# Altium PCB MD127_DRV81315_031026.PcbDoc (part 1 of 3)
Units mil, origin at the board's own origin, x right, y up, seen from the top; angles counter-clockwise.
Board outline 4400.04 x 2800.87 mil, 2 copper layers (Top Layer, Bottom Layer), stack 64.712 mil thick; 156 components, 62 nets, 376 pads, 751 vias.
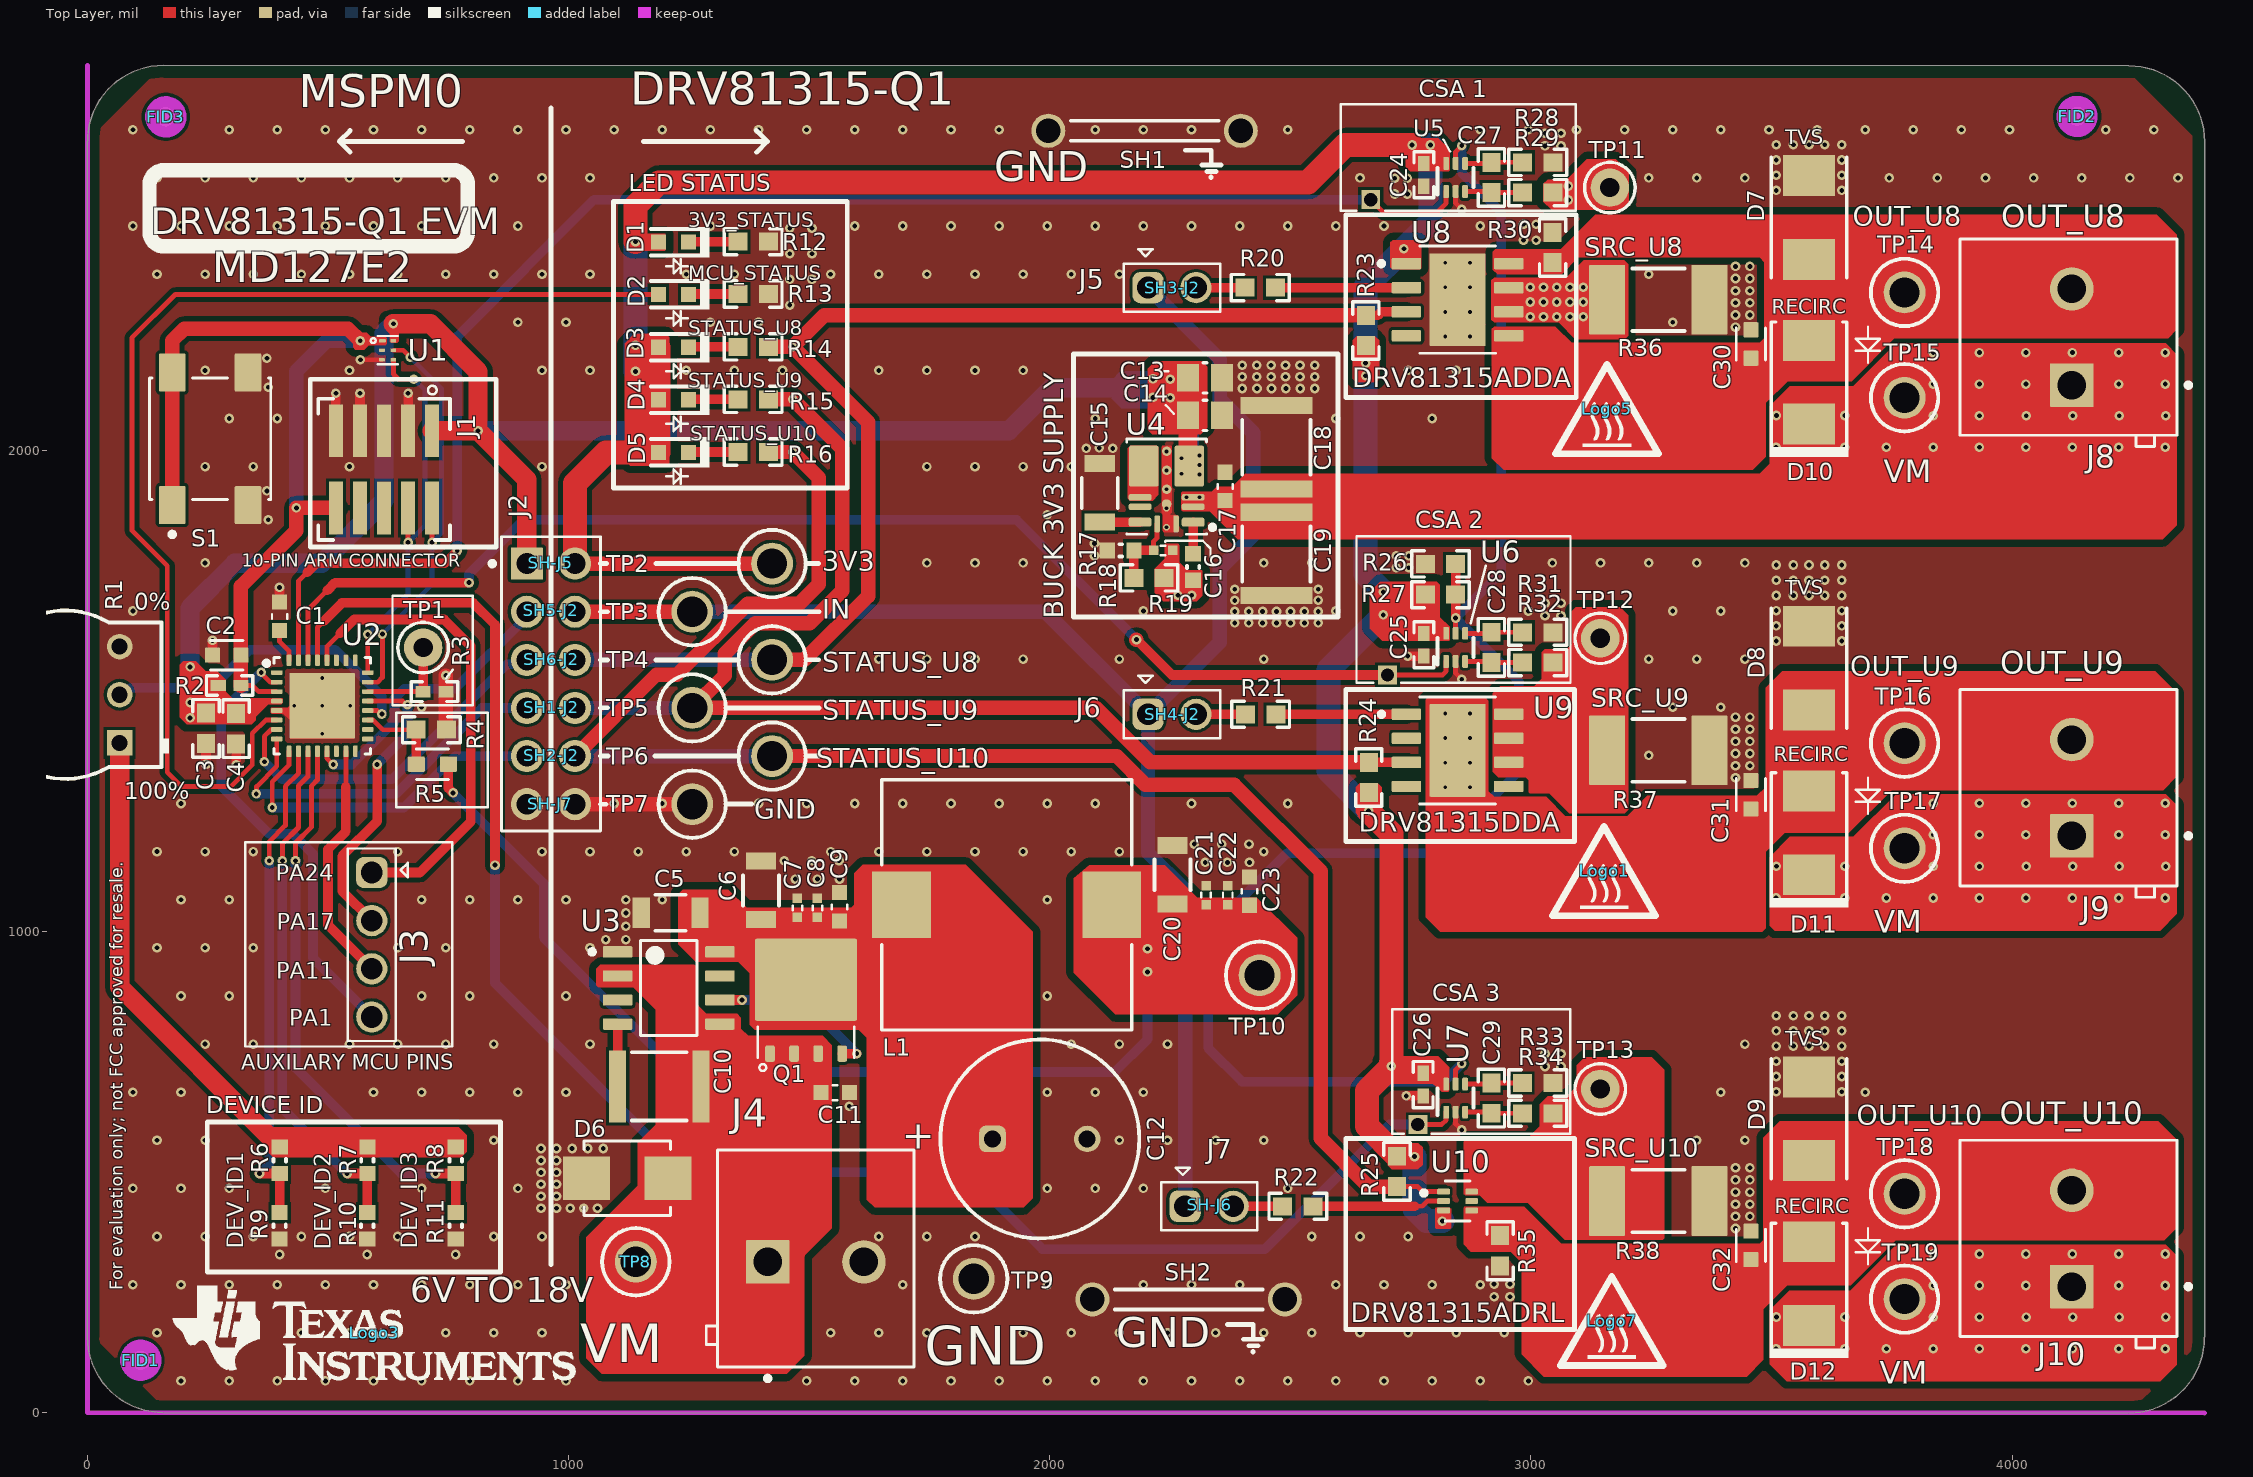
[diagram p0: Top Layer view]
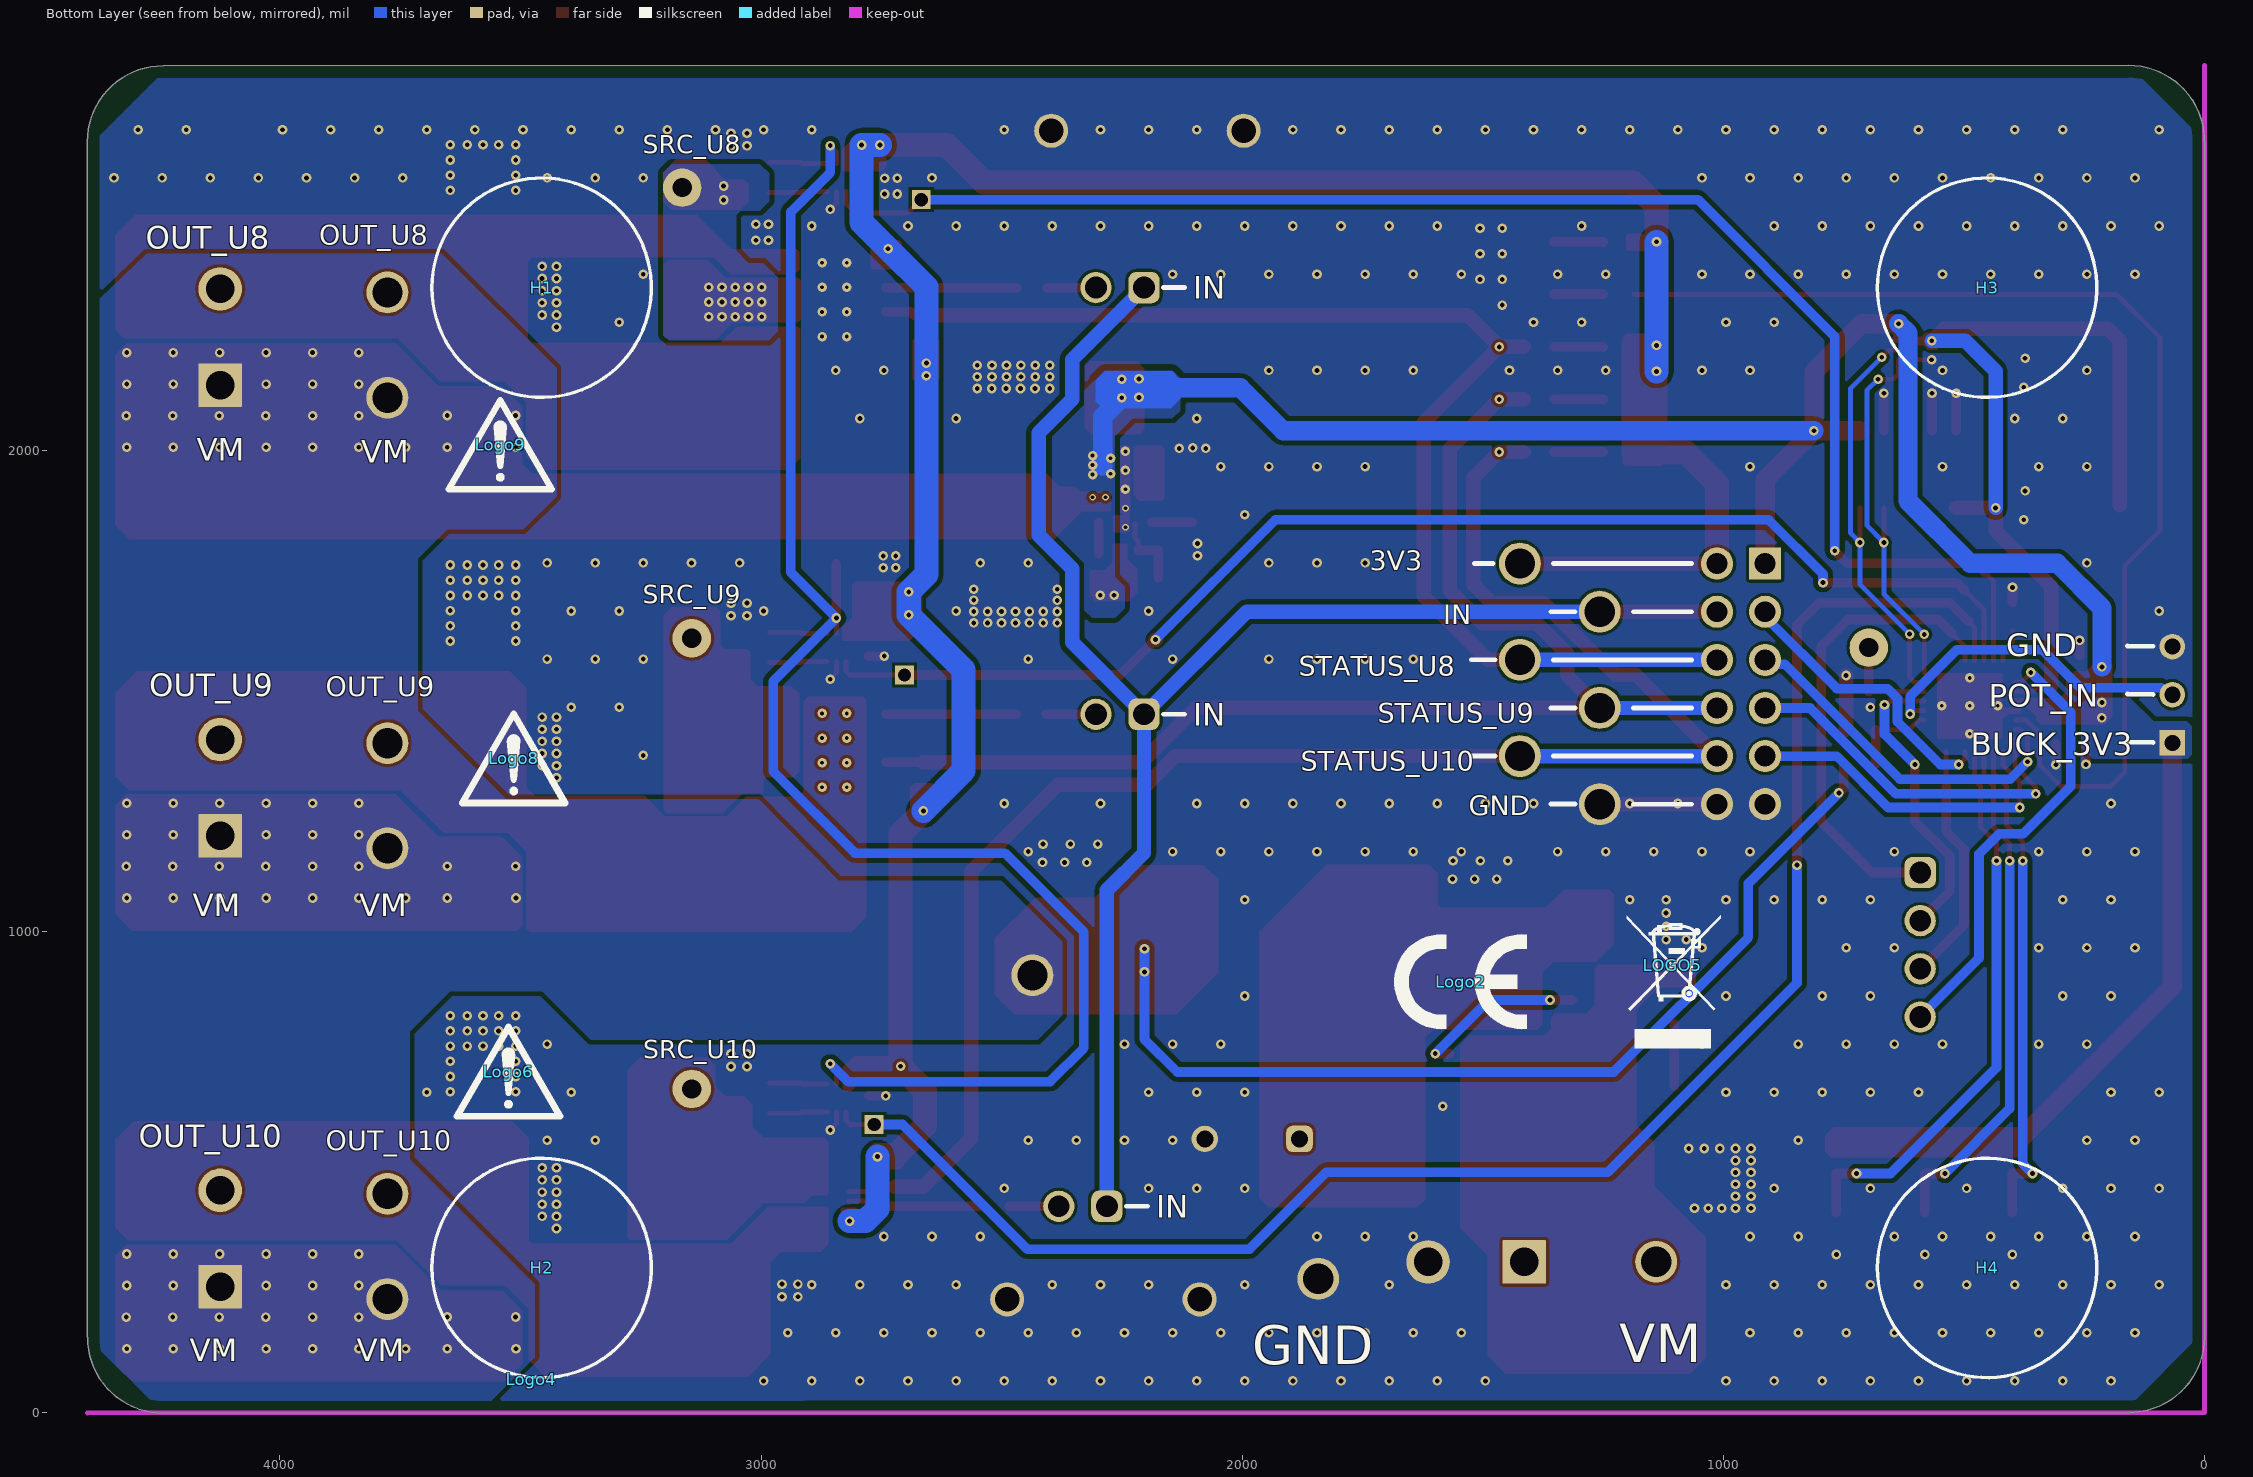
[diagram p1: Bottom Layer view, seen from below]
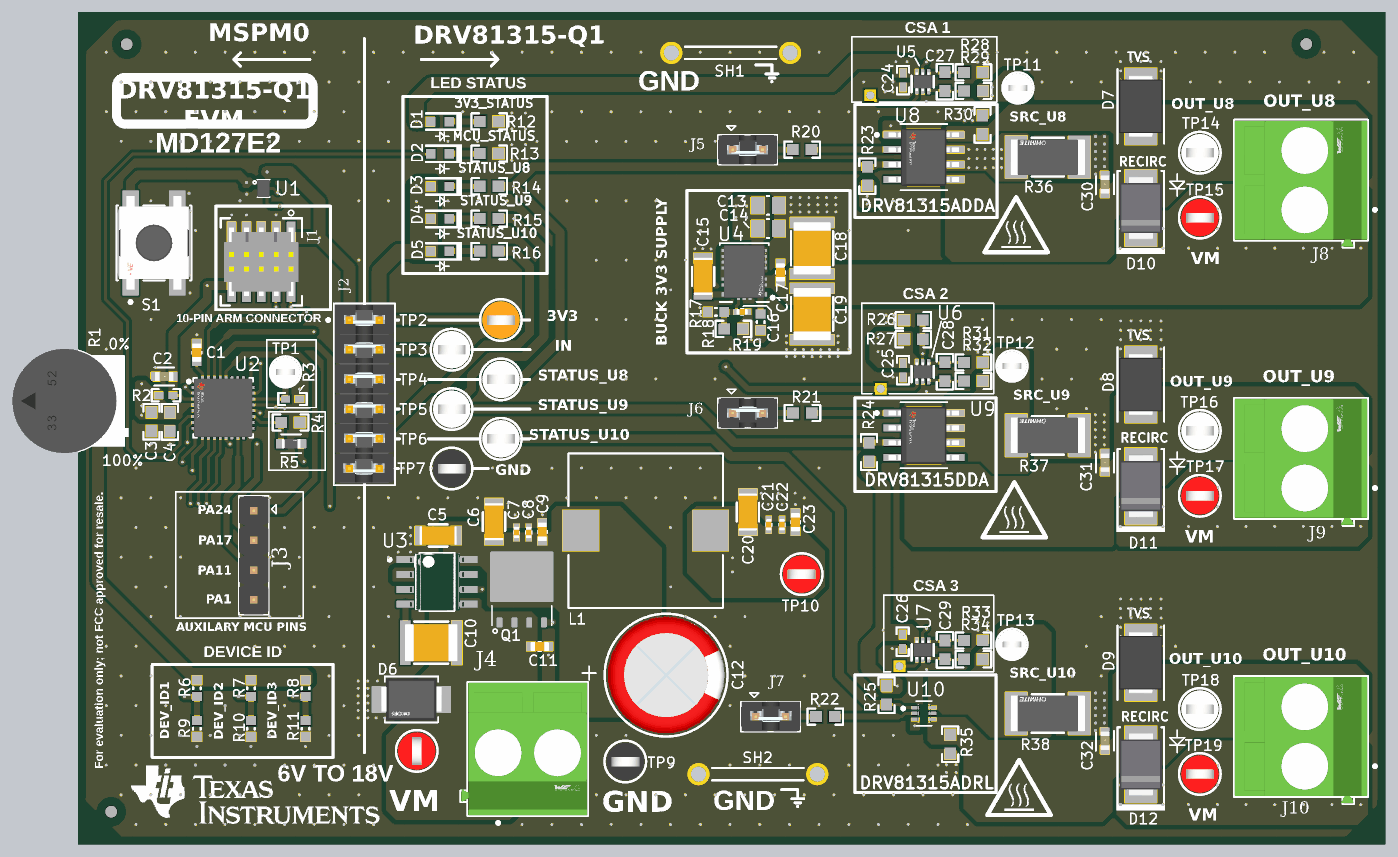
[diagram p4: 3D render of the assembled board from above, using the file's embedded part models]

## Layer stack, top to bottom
Top Solder: solder mask 0.4, Solder Resist, Dk 3.5
Top Layer: signal copper 2.756
Dielectric1: core 59.2, FR-4 High Tg, Dk 4.8
Bottom Layer: signal copper 2.756
Bottom Solder: solder mask 0.4, Solder Resist, Dk 3.5

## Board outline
157.47,0.36 cw(c157.47,157.84) -0.01,157.84 -0.04,157.84 0,2642.49 0.37,2642.49 cw(c157.85,2642.49) 157.85,2799.97 4242.57,2799.1 4242.52,2799.04 cw(c4242.52,2641.56) 4400,2641.56 4400,156.58 4399.59,156.58 cw(c4242.11,156.58) 4242.11,-0.9 4242.52,-0.9

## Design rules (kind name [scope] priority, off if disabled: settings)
AcuteAngle [All] p1: minimum=4.50000000000000E+0001 checktracksonly=FALSE
AssemblyTestPointUsage [All] p1: valid=2
BoardOutlineClearance BoardOutlineClearance_MountingHoles [OnCopper and InComponentClass('Mounting Holes')] p1: gap=15 ignorepadtopadclearanceinfootprint=FALSE
BoardOutlineClearance BoardOutlineClearance_Poly [OnCopper and IsPoly] p2: gap=25 ignorepadtopadclearanceinfootprint=FALSE
BoardOutlineClearance [OnCopper and Not InComponentClass('Logo') and not InComponentClass('FiducialMark') and not InRegion(1000,500,4000,800) and not InPoly] p3: gap=15 ignorepadtopadclearanceinfootprint=FALSE
Clearance [All] p1: gap=6 ignorepadtopadclearanceinfootprint=TRUE except(10: Track-Poly Poly-Poly; 15: Poly-Region)
Clearance Clearance_Keepouts [((IsTrack Or IsArc) And Not InPoly) And IsFree and IsKeepOut vs ((IsTrack Or IsArc) And Not InPoly) And IsFree and IsKeepOut] p2: gap=0 ignorepadtopadclearanceinfootprint=FALSE
Clearance Clearance_Poly [InPolygon] p3: gap=10 ignorepadtopadclearanceinfootprint=TRUE
Clearance Clearance_FiducialMark [IsKeepOut and InComponentClass('FiducialMark') vs IsPad and InComponentClass('FiducialMark')] p4: gap=0 ignorepadtopadclearanceinfootprint=TRUE
ComponentClearance ComponentClearance_Shunt [InComponentClass('Header') vs InComponentClass('Shunt')] p1: gap=0 collisioncheckmode=3 verticalgap=0 showdistances=FALSE
ComponentClearance ComponentClearance_PI_FILTER_R75 [InComponent('R75') vs InComponent('L1')] p2: gap=0 collisioncheckmode=3 verticalgap=0 showdistances=FALSE
ComponentClearance ComponentClearance_PI_FILTER_R66 [InComponent('R66') vs InComponent('L1')] p3: gap=0 collisioncheckmode=3 verticalgap=0 showdistances=FALSE
ComponentClearance ComponentClearance_CANL_Choke [InComponent('L2') vs InComponent('R71')] p4: gap=0 collisioncheckmode=3 verticalgap=0 showdistances=FALSE
ComponentClearance ComponentClearance_CANH_Choke [InComponent('L2') vs InComponent('R68')] p5: gap=0 collisioncheckmode=3 verticalgap=0 showdistances=FALSE
ComponentClearance ComponentClearance_MountingHoles_FiducialMarks [InComponentClass('Mounting Holes') vs InComponentClass('FiducialMark')] p6: gap=50 collisioncheckmode=3 verticalgap=10 showdistances=FALSE
ComponentClearance ComponentClearance_Logo [InComponentClass('Logo')] p7: gap=30 collisioncheckmode=3 verticalgap=10 showdistances=FALSE
ComponentClearance ComponentClearance_ScrewToNut [(HasFootprint('NY PMS 440 0025 PH')) vs (HasFootprint('Keystone_1902C'))] p8: gap=5 collisioncheckmode=3 verticalgap=10 showdistances=FALSE
ComponentClearance ComponentClearance_MountingHoles [InComponentClass('Mounting Holes')] p9: gap=100 collisioncheckmode=3 verticalgap=100000 showdistances=FALSE
ComponentClearance ComponentClearance_SmallPassives [HasFootprint('0201*') or HasFootprint('0402*') or HasFootprint('0508') or HasFootprint('0603*') or HasFootprint('0612') or HasFootprint('0805*') or HasFootprint('0815*') or HasFootprint('0830*') or HasFootprint('1206*') or HasFootprint('1210*') or HasFootprint('1808*') or HasFootprint('1812*') or HasFootprint('1825*') or HasFootprint('2010*') or HasFootprint('2220*') or HasFootprint('2225*') or HasFootprint('2512*') or HasFootprint('2728*') or HasFootprint('3518*') vs HasFootprint('0201*') or HasFootprint('0402*') or HasFootprint('0508') or HasFootprint('0603*') or HasFootprint('0612') or HasFootprint('0805*') or HasFootprint('0815*') or HasFootprint('0830*') or HasFootprint('1206*') or HasFootprint('1210*') or HasFootprint('1808*') or HasFootprint('1812*') or HasFootprint('1825*') or HasFootprint('2010*') or HasFootprint('2220*') or HasFootprint('2225*') or HasFootprint('2512*') or HasFootprint('2728*') or HasFootprint('3518*')] p10: gap=14.96 collisioncheckmode=3 verticalgap=10 showdistances=FALSE
ComponentClearance ComponentClearance_THtoSMT [IsThruComponent vs IsSMTComponent] p11: gap=30 collisioncheckmode=3 verticalgap=30 showdistances=FALSE
ComponentClearance ComponentClearance_THtoTH [IsThruComponent vs IsThruComponent] p12: gap=20 collisioncheckmode=3 verticalgap=30 showdistances=FALSE
ComponentClearance [All] p13: gap=20 collisioncheckmode=3 verticalgap=10 showdistances=FALSE
DiffPairsRouting [All] p1: maxlimit=100 minlimit=10 mostfreqgap=10 toplayer_minwidth=6 toplayer_maxwidth=15 toplayer_prefwidth=10 bottomlayer_minwidth=6 bottomlayer_maxwidth=15 bottomlayer_prefwidth=10 maxuncoupledlength=1000
FabricationTestPointUsage TestPointUsage [All] p1: valid=2 allowmultiple=FALSE
FabricationTestpoint Testpoint [All] p1: side=3 testpointundercomponent=TRUE minsize=40 maxsize=100 preferedsize=60 minholesize=0 maxholesize=40 preferedholesize=32 testpointgrid=1 allowsidetop=TRUE allowsidebottom=TRUE usegrid=TRUE gridtolerance=0.01
FanoutControl Fanout_LCC [IsLCC] p1: bgadir=Out bgaviamode=Centered fanoutstyle=Auto fanoutdirection=Alternating viagrid=1 // Fanout_LCC (Default Rule)
FanoutControl Fanout_BGA [IsBGA] p2: bgadir=Out bgaviamode=Centered fanoutstyle=Auto fanoutdirection=Alternating viagrid=1 // Fanout_BGA (Default Rule)
FanoutControl Fanout_Default [All] p4: bgadir=Out bgaviamode=Centered fanoutstyle=Auto fanoutdirection=Alternating viagrid=1 // Fanout_Default (Default Rule)
FanoutControl Fanout_Small [(CompPinCount < 5)] p5: bgadir=Out bgaviamode=Centered fanoutstyle=Auto fanoutdirection=OutThenIn viagrid=1 // Fanout_Small (Default Rule)
HoleSize [All] p1: absolutevalues=TRUE maxlimit=251 minlimit=7.87 maxpercent=80.000 minpercent=20.000
MinimumAnnularRing MinimumAnnularRing_ThermalPadVias [IsVia and InAnyComponent] p1: minimumring=5.91
MinimumAnnularRing [All] p2: minimumring=5.91
MinimumSolderMaskSliver MinimumSolderMaskSliver_Logo [InComponentClass('Logo') vs InComponentClass('Logo')] p1: minsoldermaskwidth=0.7
MinimumSolderMaskSliver [All] p2: minsoldermaskwidth=3.94
PlaneClearance [All] p1: clearance=10
PlaneConnect [All] p1: planeconnectstyle=Direct reliefexpansion=10 reliefentries=4 reliefconductorwidth=10 reliefairgap=10
PolygonConnect [All] p1: connectstyle=Direct reliefconductorwidth=10 reliefentries=4 polygonreliefangle="90 Angle" airgapwidth=10
RoutingVias ThermalPadVias [IsVia and InAnyComponent] p1: holewidth=7.87 width=19.68 viastyle="Through Hole" minholewidth=7.87 minwidth=19.68 maxholewidth=12.99 maxwidth=23.62
RoutingVias [All] p2: holewidth=16 width=34 viastyle="Through Hole" minholewidth=7.87 minwidth=19.68 maxholewidth=236.22 maxwidth=236.22
SilkToBoardRegionClearance [Not ((IsComment or IsDesignator) And (Hide <> 'False')) and not InRegion(1000,500,4000,800)] p1:
SilkToSilkClearance SilkToSilkClearance_Pb-FreeLogo [(HasFootprint('Pb-Free_Overlay_Medium') OR HasFootprint('Pb-Free_Overlay_Small')) vs (HasFootprint('Pb-Free_Overlay_Medium') OR HasFootprint('Pb-Free_Overlay_Small'))] p1: silktosilkclearance=0
SilkToSilkClearance [All] p2: silktosilkclearance=3.94
SilkToSolderMaskClearance SilkToComponentPadClearance [(IsPad or IsFill or IsRegion) and InAnycomponent] p1: minsilkscreentomaskgap=5 clearancetoexposedcopper=TRUE
SilkToSolderMaskClearance "Silk to Solder Mask Opening" [All] p2: minsilkscreentomaskgap=3.94 clearancetoexposedcopper=FALSE
SolderMaskExpansion [All] p1: expansion=1.97 istentingtop=FALSE
UnRoutedNet [All] p1: checkbadconnections=TRUE
Width [All] p1: maxlimit=100 minlimit=6 preferedwidth=10 checkconnectedcopper=TRUE
13 further rules are at their usual default settings.

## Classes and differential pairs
component class DRV81315-Q1_HW: !PCB1 FID1 FID2 FID3 H1 H2 H3 H4 Logo1 Logo2 Logo3 Logo4 LOGO5 Logo6 ZZ1 ZZ2 ZZ3 ZZ4
component class DRV81315AQ1_ICs: 15 C24 C25 C26 C27 C28 C29 C30 C31 C32 D7 D8 D9 D10 D11 D12 J5 J6 J7 J8 J9 J10 L? R20 R21 R22 R23 R24 R25 R26 R27 R28 R29 R30 R31 R32 R33 R34 R35 R36 R37 R38 SH1 SH2 SH-J5 SH-J6 SH-J7 TP11 TP12 TP13 TP14 TP15 TP16 TP17 TP18 TP19 U5 U6 U7 U8 U9 U10
component class DRV81315-Q1_MCU_Supply: C1 C2 C3 C4 C5 C6 C7 C8 C9 C10 C11 C12 C13 C14 C15 C16 C17 C18 C19 C20 C21 C22 C23 D1 D2 D3 D4 D5 D6 J1 J2 J3 J4 l1 Q1 R1 R2 R3 R4 R5 R6 R7 R8 R9 R10 R11 R12 R13 R14 R15 R16 R17 R18 R19 S1 SH1-J2 SH2-J2 SH3-J2 SH4-J2 SH5-J2 SH6-J2 TP1 TP2 TP3 TP4 TP5 TP6 TP7 TP8 TP9 TP10 U1 U2 U3 U4

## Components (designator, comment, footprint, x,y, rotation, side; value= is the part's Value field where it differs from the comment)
C1 "885012206075R" WCAP-CSGP_0603_L1.6W0.8H0.8_REFLOW 399.1,1654.99 r270 top value=470nF
C2 "885012206065" FP-885012206065_0603-MFG 289.54,1574.33 r180 top value=10nF
C3 "GRM188R61E106KA73D" 0603 246.51,1422.21 r270 top value=10uF
C4 "885012206095" 0603 309,1421.5 r270 top value=0.1uF
C5 "885012208093" WCAP-CSGP_1206_L3.2W1.6H1.6 1212,1039 r0 top
C6 "885012208093" WCAP-CSGP_1206_L3.2W1.6H1.6 1399.91,1085.54 r270 top
C7 "885012205067" WCAP-CSGP_0402_L1W0.5H0.5 1475.5,1049.2 r270 top
C8 "885012205061" WCAP-CSGP_0402_L1W0.5H0.5 1516.92,1049.2 r270 top
C9 "885012206095" WCAP-CSGP_0603_L1.6W0.8H0.8_REFLOW 1562.71,1051.38 r270 top
C10 "885012210032" WCAP-CSGP_1812_L4.5W3.2H2.5 1188.46,678.32 r0 top
C11 "885012206091" WCAP-CSGP_0603_L1.6W0.8H0.8_REFLOW 1554,665.09 r180 top
C12 "860040875004" WCAP-ATUL_D10H20 1979.38,568.96 r180 top
C13 "885012107014" 0805_150 2322.72,2150.59 r0 top value=10uF
C14 "885012107014" 0805_150 2322.72,2072.53 r0 top value=10uF
C15 "885012208093" WCAP-CSGP_1206_L3.2W1.6H1.6 2103.93,1911.73 r270 top
C16 "885012005029" WCAP-CSGP_0402_L1W0.5H0.5 2235.56,1792.13 r0 top
C17 "885012206095" WCAP-CSGP_0603_L1.6W0.8H0.8_REFLOW 2364.37,1924.96 r270 top
C18 "885012210032" WCAP-CSGP_1812_L4.5W3.2H2.5 2471.06,2006.19 r270 top
C19 "885012210032" WCAP-CSGP_1812_L4.5W3.2H2.5 2471.06,1784.67 r90 top
C20 "885012208093" WCAP-CSGP_1206_L3.2W1.6H1.6 2255,1118 r270 top
C21 "885012205067" WCAP-CSGP_0402_L1W0.5H0.5 2324.7,1075.68 r270 top
C22 "885012205061" WCAP-CSGP_0402_L1W0.5H0.5 2369.89,1075.68 r270 top
C23 "885012206095" WCAP-CSGP_0603_L1.6W0.8H0.8_REFLOW 2414.78,1084.07 r270 top
C24 "885012105001" 0402 2777.36,2572.55 r90 top value=0.1uF
C25 "885012105001" 0402 2777.36,1595.92 r90 top value=0.1uF
C26 "885012105001" 0402 2775.95,681.93 r90 top value=0.1uF
C27 "885012206046" 0603 2917.89,2567.04 r90 top value=0.1uF
C28 "885012206046" 0603 2917.89,1590.41 r90 top value=0.1uF
C29 "885012206046" 0603 2917.89,653.78 r90 top value=0.1uF
C30 "885012206091" FP-885012206091_0603-MFG 3457,2221 r270 top value=22nF
C31 "885012206091" FP-885012206091_0603-MFG 3457,1284.37 r270 top value=22nF
C32 "885012206091" FP-885012206091_0603-MFG 3457,347.74 r270 top value=22nF
D1 "150060VS75000" WL-SMCW_GREEN 1218.01,2432.69 r180 top value=Green
D2 "150060VS75000" WL-SMCW_GREEN 1218.01,2324.12 r180 top value=Green
D3 "150060RS75000" WL-SMCW_RED 1218.01,2214.23 r180 top value=Red
D4 "150060RS75000" WL-SMCW_RED 1218.01,2105 r180 top value=Red
D5 "150060RS75000" WL-SMCW_RED 1218.01,1995.77 r180 top
D6 "SMBJ36CA-13-F" FP-SMBJ36CA-13-F_SMB-MFG 1122,487.09 r180 top
D7 "SMBJ33CA-13-F" SMB-Bi 3577.88,2484.01 r270 top value=33V
D8 "SMBJ33CA-13-F" SMB-Bi 3577.88,1547.38 r270 top value=33V
D9 "SMBJ33CA-13-F" SMB-Bi 3577.88,610.74 r270 top value=33V
D10 "SS24T3G" SMB 3577.88,2141.62 r90 top value=40V
D11 "SS24T3G" SMB 3577.88,1204.99 r90 top value=40V
D12 "SS24T3G" SMB 3577.88,268.36 r90 top value=40V
FID1 "Fiducial" Fiducial10-20 111,109 r0 top
FID2 "Fiducial" Fiducial10-20 4135,2693.92 r0 top
FID3 "Fiducial" Fiducial10-20 163,2693 r0 top
H1 "SJ-5303 (CLEAR)" Bumpon_SJ5003Transparent 3456,2338 r180 bottom
H2 "SJ-5303 (CLEAR)" Bumpon_SJ5003Transparent 3456,301 r180 bottom
H3 "SJ-5303 (CLEAR)" Bumpon_SJ5003Transparent 452,2338 r180 bottom
H4 "SJ-5303 (CLEAR)" Bumpon_SJ5003Transparent 452,301 r180 bottom
J1 "FTSH-105-01-L-DV-K" SAMTEC_FTSH-105-01-X-DV-K 616.46,1960.48 r270 top
J2 "61301221121" FP-61301221121_HDR12-MFG 963.3,1514.56 r270 top
J3 "61300411121" WURTH_61300411121 591,972.52 r270 top
J4 "691236510002" FP-691236510002_HHR2-MFG#1 1501.92,320.2 r0 top
J5 "61300211121" WURTH_61300211121 2254.12,2338.11 r0 top
J6 "61300211121" WURTH_61300211121 2254.12,1451.48 r0 top
J7 "61300211121" WURTH_61300211121 2331.28,429 r0 top
J8 "691236510002" FP-691236510002_HHR2-MFG#2 4117.18,2223.6 r90 top
J9 "691236510002" FP-691236510002_HHR2-MFG#2 4117.18,1286.97 r90 top
J10 "691236510002" FP-691236510002_HHR2-MFG#2 4117.18,350.33 r90 top
L1 "74437377010" WE-LHMI_1335 1910.49,1055.44 r0 top value=1uH
Logo1 "CAUTION HOT SURFACE" IEC_HotSurface_Small 3152,1126 r0 top (schematic designator LOGO1)
Logo2 "CE Mark" CE_Mark_5mm 1546.13,895.63 r180 bottom
Logo3 "Texas Instruments" TI_Stacked_Overlay_Small 596,166 r0 top
Logo4 "FCC disclaimer" FCC_disclaimer 3478,69.09 r180 bottom
Logo5 "CAUTION HOT SURFACE" IEC_HotSurface_Small 3158,2086 r0 top (schematic designator LOGO1)
LOGO5 "WEEE logo" WEEE_Minimum 1105.27,929.45 r180 bottom (schematic designator Logo5)
Logo6 "CAUTION.  READ USER GUIDE BEFORE USE" IEC_Caution_Small 3525,709 r180 bottom
Logo7 "CAUTION HOT SURFACE" IEC_HotSurface_Small 3168,191 r0 top (schematic designator LOGO1)
Logo8 "CAUTION.  READ USER GUIDE BEFORE USE" IEC_Caution_Small 3514,1360 r180 bottom (schematic designator Logo6)
Logo9 "CAUTION.  READ USER GUIDE BEFORE USE" IEC_Caution_Small 3542,2012 r180 bottom (schematic designator Logo6)
Q1 "CSD19502Q5B" DNK0008A 1493.58,857.23 r90 top value=80V
R1 "3352T-1-503LF" Bourns_3352T 67,1492.09 r90 top value=50k
R2 "CRCW040247K0JNED" 0402 295.45,1511.18 r180 top value=47k
R3 "CRCW040247K0JNED" 0402 721.37,1498.53 r180 top value=47k
R4 "RC0603JR-071KL" 0603 714.83,1419.47 r180 top value=1.0k
R5 "RT0603BRE078KL" FP-RT0603BRE078KL_0603-MFG 716.83,1347.75 r0 top value=8k
R6 "RC0603JR-0710KL" 0603L 399.78,524.72 r270 top value=10k
R7 "RC0603JR-0710KL" 0603L 581.76,524.72 r270 top value=10k
R8 "RC0603JR-0710KL" 0603L 765.55,524.72 r270 top value=10k
R9 "RC0603JR-0710KL" 0603L 399.48,388.42 r270 top value=10k
R10 "RC0603JR-0710KL" 0603L 581.6,388.42 r270 top value=10k
R11 "RC0603JR-0710KL" 0603L 765.55,388.42 r270 top value=10k
R12 "RC0603FR-071KL" 0603 1383.61,2433.49 r180 top value=1.00k
R13 "RC0603JR-07330RL" 0603 1383.62,2324.91 r180 top value=330
R14 "RC0603JR-07330RL" 0603 1383.61,2215.03 r180 top value=330
R15 "RC0603JR-07330RL" 0603 1383.61,2105.8 r180 top value=330
R16 "RC0603JR-07330RL" 0603 1383.61,1996.56 r180 top value=330
R17 "RC0603JR-0710KL" 0603L 2147.14,1792.13 r0 top value=10k
R18 "RC0603FR-0723K2L" 0603 2206.2,1734.88 r0 top value=23.2k
R19 "RC0603JR-0710KL" 0603L 2297.87,1757.52 r270 top value=10k
R20 "RC0603FR-071KL" 0603 2437.45,2338.11 r0 top value=1.00k
R21 "RC0603FR-071KL" 0603 2438.34,1451.48 r0 top value=1.00k
R22 "RC0603FR-071KL" 0603 2515.5,429 r0 top value=1.00k
R23 "RC0603FR-074K99L" 0603 2657,2249 r90 top value=4.99k
R24 "RC0603FR-074K99L" 0603 2663,1319.98 r90 top value=4.99k
R25 "RC0603FR-074K99L" 0603 2721.62,501.41 r270 top value=4.99k
R26 "RC0603FR-07200RL" 0603 2811.87,1764 r0 top value=200
R27 "RC0603FR-07200RL" 0603 2811.87,1700 r180 top value=200
R28 "ERJ-3GEY0R00V" 0603 3014.16,2598.54 r180 top value=0
R29 "ERJ-3GEY0R00V" 0603 3014.16,2535.54 r180 top value=0
R30 "RC0603FR-07100KL" 0603 3045,2421.5 r270 top value=100k
R31 "ERJ-3GEY0R00V" 0603 3014.16,1621.9 r180 top value=0
R32 "ERJ-3GEY0R00V" 0603 3014.16,1558.91 r180 top value=0
R33 "ERJ-3GEY0R00V" 0603 3014.16,685.27 r180 top value=0
R34 "ERJ-3GEY0R00V" 0603 3014.16,622.28 r180 top value=0
R35 "RC0603FR-07100KL" 0603 2936,336.5 r90 top value=100k
R36 "PCS2512DR0100ET" FP-PCS2512DR0100ET_2512-MFG 3264.7,2313.11 r180 top
R37 "PCS2512DR0100ET" FP-PCS2512DR0100ET_2512-MFG 3264.7,1376.48 r180 top
R38 "PCS2512DR0100ET" FP-PCS2512DR0100ET_2512-MFG 3264.7,439.84 r180 top
S1 "430481025816" FP-430481025816_SMT_SW_6MM2_6MM2-MFG 255,2024 r90 top
SH1 "Jumper_2p" Harwin_D3082-05 2197,2664.09 r180 top
SH1-J2 "60900213421" Wurth_60900213421 963.77,1466.24 r0 top
SH2 "Jumper_2p" Harwin_D3082-05 2288.48,235.42 r180 top
SH2-J2 "60900213421" Wurth_60900213421 963.77,1366.24 r0 top
SH3-J2 "60900213421" Wurth_60900213421 2254.12,2338.11 r180 top
SH4-J2 "60900213421" Wurth_60900213421 2254.12,1451.48 r0 top
SH5-J2 "60900213421" Wurth_60900213421 963.3,1667.74 r0 top
SH6-J2 "60900213421" Wurth_60900213421 963.77,1566.24 r0 top
SH-J5 "60900213421" Wurth_60900213421 963.3,1766.34 r180 top
SH-J6 "60900213421" Wurth_60900213421 2332.29,432.05 r180 top
SH-J7 "60900213421" Wurth_60900213421 962.02,1265.79 r180 top
TP1 "5002" Keystone5002 697.75,1590 r90 top
TP2 "5013" Keystone5013 1422.91,1764.69 r90 top
TP3 "5012" Keystone5012 1257.04,1664.69 r90 top
TP4 "5012" Keystone5012 1422.91,1564.69 r90 top
TP5 "5012" Keystone5012 1257.04,1464.69 r90 top
TP6 "5012" Keystone5012 1422.91,1364.69 r90 top
TP7 "5011" Keystone5011 1257.04,1264.69 r90 top
TP8 "5010" Keystone5010 1139.79,313.78 r0 top
TP9 "5011" Keystone5011 1842,278.09 r90 top
TP10 "5010" Keystone5010 2436,909 r270 top
TP11 "5002" Keystone5002 3164,2546 r90 top
TP12 "5002" Keystone5002 3144,1609.37 r90 top
TP13 "5002" Keystone5002 3144,672.74 r90 top
TP14 "5012" Keystone5012 3776.4,2328.08 r90 top
TP15 "5010" Keystone5010 3776.4,2109.4 r90 top
TP16 "5012" Keystone5012 3776.4,1391.45 r90 top
TP17 "5010" Keystone5010 3776.4,1172.77 r90 top
TP18 "5012" Keystone5012 3776.4,454.82 r90 top
TP19 "5010" Keystone5010 3776.4,236.14 r90 top
U1 "TPD4E004DRYR" DRY0006A 624,2208 r0 top
U2 "MSPM0G3507SRHB" RHB0032E-MFG 488,1469 r0 top
U3 "LM74700QDRQ1" D0008A-MFG 1208.15,882.65 r0 top
U4 "TPSM365R3FRDNR" RDN0011A-MFG 2242.76,1927.95 r180 top
U5 "INA185A2IDRLR" DRL0006A 2843.37,2567.04 r90 top
U6 "INA185A2IDRLR" DRL0006A 2843.37,1590.41 r90 top
U7 "INA185A2IDRLR" DRL0006A 2843.37,653.78 r90 top
U8 "DRV81315ADDA" DDA0008B-MFG 2847.5,2313.11 r0 top
U9 "DRV81315DDA" DDA0008B-MFG 2847.5,1376.48 r0 top
U10 "DRV81315ADRL" DRL0006A-MFG 2847.5,439.84 r0 top
ZZ1 "This Assembly Note is for PCB labels only" AssemblyNoteLabel -521.96,6760.09 r0 top
ZZ2 "These assemblies are ESD sensitive, ESD precautions shall be observed." AssemblyNote -517,6642.09 r0 top
ZZ3 "These assemblies must be clean and free from flux and all contaminants. Use of no clean flux is not acceptable." AssemblyNote -518,6517.09 r0 top
ZZ4 "These assemblies must comply with workmanship standards IPC-A-610 Class 2, unless otherwise specified." AssemblyNote -518,6372.09 r0 top

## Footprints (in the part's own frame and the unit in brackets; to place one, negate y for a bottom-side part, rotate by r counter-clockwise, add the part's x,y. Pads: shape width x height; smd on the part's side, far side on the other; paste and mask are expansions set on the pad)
0402 [mm] "0402 from SM-752 data"
  rect 0.8x0.6 smd: 1(-0.6,0) 2(0.6,0)
  silkscreen extent -1.22,-0.52 1.22,0.52, body extent -0.55,-0.3 0.55,0.3, height 0.6
0603 [mm] "0603 from SM-752 data"
  rect 1x0.95 smd: 1(-0.8,0) 2(0.8,0)
  silkscreen extent -1.52,-0.69 1.52,0.69, body extent -0.87,-0.47 0.87,0.47, height 1
0603L [mm] "0603 from SM-752 data"
  rect 0.8x0.85 smd: 1(-0.7,0) 2(0.7,0)
  silkscreen extent -0.07,-0.33 0.07,0.33, body extent -0.87,-0.47 0.87,0.47, height 1
0805_150 [mm] "0805 / 1.5 mm height"
  rect 1.15x1.45 smd: 1(-0.9,0) 2(0.9,0)
  silkscreen extent -0.1,-0.8 0.1,0.8, body extent -1.1,-0.72 1.1,0.72, height 1.5
AssemblyNote [mil] "Assembly Note"
AssemblyNoteLabel [mil] "Assembly Note for PCB Labels"
Bourns_3352T [mm] "TH, 3-Leads, Body 9.53x8.89mm, Pitch 2.54mm"
  rect 1.35x1.35 hole 0.85: 1(-2.54,0)
  round 1.35 hole 0.85: 2(0,0) 3(2.54,0)
  silkscreen extent -4.44,-2.6 4.44,7.31, body extent -4.44,-2.21 4.45,7.32, height 3.81
Bumpon_SJ5003Transparent [mil] "3M Hemispherical Bumpon transparent"
  round 1 on Mech4: 0(0,0)
  silkscreen extent -228,-228 228,228, body extent -219,-219 219,219, height 197
CE_Mark_5mm [mil] "Minimum text height for CE Mark"
  silkscreen extent -138,-98 138,98
D0008A-MFG [mm] "Recommended Land Pattern"
  rrect17% 1.55x0.6 smd paste+0 mask+0: 1(-2.7,1.905) 2(-2.7,0.635) 3(-2.7,-0.635) 4(-2.7,-1.905) 5(2.7,-1.905) 6(2.7,-0.635) 7(2.7,0.635) 8(2.7,1.905)
  silkscreen extent -4.17,-2.5 1.5,2.5, body extent -3,-2.45 3,2.45, height 1.75
DDA0008B-MFG [mm] "Recommended Land Pattern"
  rrect17% 1.55x0.6 smd: 1(-2.7,1.905) 2(-2.7,0.635) 3(-2.7,-0.635) 4(-2.7,-1.905) 5(2.7,-1.905) 6(2.7,-0.635) 7(2.7,0.635) 8(2.7,1.905)
  rrect3% 2.95x4.9 smd: 9(0,0)
  silkscreen extent -4.15,-2.83 2,2.83, body extent -3.01,-2.45 3.01,2.45, height 1.7
DNK0008A [mm] "SON, 8-Leads, Body 5x6mm"
  rrect39% 0.86x0.51 smd paste+0 mask+0: 1(-2.82,1.905) 2(-2.82,0.635) 3(-2.82,-0.635) 4(-2.82,-1.905)
  rrect39% 0.86x0.51 smd paste-0.05 mask-0.05: 5(2.82,-1.905) 6(2.82,-0.635) 7(2.82,0.635) 8(2.82,1.905)
  rrect50% 0.25x0.555 on Top Paste: 9(-0.83,2.372) 9(-0.83,-2.372)
  rrect50% 0.25x0.555 on Top Solder: 9(-0.83,2.372) 9(-0.83,-2.372)
  rrect50% 0.95x1.13 on Top Paste: 9(-0.535,0) 9(-0.535,1.33) 9(-0.535,-1.33) 9(0.615,0) 9(0.615,-1.33) 9(0.615,1.33) 9(1.765,-1.33) 9(1.765,1.33) 9(1.765,0)
  rrect50% 3.58x4 on Top Solder: 9(0.75,0)
  rrect5% 4.34x5.4 smd paste+0 mask+0: 9(1.08,0)
  silkscreen extent -3.74,-2.55 -1.41,2.55, body extent -3.05,-2.55 3.05,2.55, height 1.06
DRL0006A [mm] "SOTFL, 6-Flat Leads, Body 1.2x1.6x0.6mm, Pitch 0.5mm, TI recommended"
  rrect33% 0.67x0.3 smd: 1(-0.74,0.5) 2(-0.74,0) 3(-0.74,-0.5) 4(0.74,-0.5) 5(0.74,0) 6(0.74,0.5)
  silkscreen extent -0.9,-0.95 0.5,0.95, body extent -0.8,-0.8 0.8,0.8, height 0.61
DRL0006A-MFG [mm] "Recommended Land Pattern"
  rrect33% 0.67x0.3 smd: 1(-0.74,0.5) 2(-0.74,0) 3(-0.74,-0.5) 4(0.74,-0.5) 5(0.74,0) 6(0.74,0.5)
  silkscreen extent -1.9,-1.05 0.65,1.05, body extent -0.8,-0.8 0.8,0.8, height 0.6
DRY0006A [mm] "PSON, 6-Leads, Body 1x1.45mm, Pitch 0.5mm, TI Recommended"
  rrect50% 0.35x0.2 smd mask+0.038: 1(-0.275,0.5)
  rrect50% 0.3x0.2 smd mask+0.038: 2(-0.3,0) 3(-0.3,-0.5) 4(0.3,-0.5) 5(0.3,0) 6(0.3,0.5)
  silkscreen extent -0.89,-0.75 0.53,0.75, body extent -0.5,-0.72 0.5,0.73, height 0.58
FCC_disclaimer [mil]
Fiducial10-20 [mm]
  round 1 smd: 1(0,0)
  Top Layer keep-out circle w1.178: c0,0 r0.5
FP-61301221121_HDR12-MFG [mm]
  rrect6% 1.7x1.7 hole 1.1 paste-2539.97 mask+0: 1(-6.35,-1.27)
  round 1.7 hole 1.1 paste-2539.97 mask+0: 2(-6.35,1.27) 3(-3.81,-1.27) 4(-3.81,1.27) 5(-1.27,-1.27) 6(-1.27,1.27) 7(1.27,-1.27) 8(1.27,1.27) 9(3.81,-1.27) 10(3.81,1.27) 11(6.35,-1.27) 12(6.35,1.27)
  silkscreen extent -7.77,-3.22 7.77,2.62, body extent -7.87,-2.72 7.87,2.72, height 0.25
FP-430481025816_SMT_SW_6MM2_6MM2-MFG [mm]
  rrect7% 2x1.4 smd paste+0 mask+0: 1(-3.5,2) 2(3.5,2) 3(-3.5,-2) 4(3.5,-2)
  silkscreen extent -5.17,-3.2 3.2,3.2, body extent -4.6,-3.3 4.6,3.3, height 0.25
FP-691236510002_HHR2-MFG#1 [mm]
  rrect4% 2.3x2.3 hole 1.5 paste-2539.97 mask+0: 1(-2.24,-0.175)
  round 2.3 hole 1.5 paste-2539.97 mask+0: 2(2.84,-0.175)
  silkscreen extent -5.48,-6.45 5.48,5.72, body extent -5.58,-5.82 5.58,5.82, height 0.25
FP-691236510002_HHR2-MFG#2 [mm]
  rrect4% 2.3x2.3 hole 1.5: 1(-2.24,-0.175)
  round 2.3 hole 1.5: 2(2.84,-0.175)
  silkscreen extent -5.48,-6.45 5.48,5.72, body extent -5.58,-5.82 5.58,5.82, height 0.25
FP-885012206065_0603-MFG [mm]
  rrect13% 0.8x0.8 smd: 1(-0.75,0) 2(0.75,0)
  silkscreen extent -0.85,-0.77 0.85,0.77, body extent -1.25,-0.55 1.25,0.55, height 0.25
FP-885012206091_0603-MFG [mm]
  rrect13% 0.8x0.8 smd: 1(-0.75,0) 2(0.75,0)
  silkscreen extent -0.85,-0.77 0.85,0.77, body extent -1.25,-0.55 1.25,0.55, height 0.25
FP-PCS2512DR0100ET_2512-MFG [mm]
  rrect5% 1.9x3.68 smd: 1(-2.7,0) 2(2.7,0)
  silkscreen extent -1.38,-1.65 1.38,1.65, body extent -3.75,-1.94 3.75,1.94, height 0.25
FP-RT0603BRE078KL_0603-MFG [mm]
  rrect13% 0.9x0.8 smd: 1(-0.85,0) 2(0.85,0)
  silkscreen extent -0.85,-0.81 0.86,0.8, body extent -1.4,-0.55 1.4,0.55, height 0.25
FP-SMBJ36CA-13-F_SMB-MFG [mm]
  rrect4% 2.5x2.3 smd paste+0 mask+0: 1(-2.15,0) 2(2.15,0)
  silkscreen extent -2.28,-1.97 2.28,1.97, body extent -3.5,-2.07 3.5,2.07, height 0.25
Harwin_D3082-05 [mm] "Shorting Plug, 10.16mm spacing, TH"
  round 1.8 hole 1.3: 1(-5.08,0) 2(5.08,0)
  silkscreen extent -3.9,-0.53 3.9,0.53, body extent -5.6,-0.52 5.61,0.52, height 6.63
IEC_Caution_Small [mil]
  silkscreen extent -107,-93 107,92
IEC_HotSurface_Small [mil]
  silkscreen extent -107,-93 107,92
Keystone5002 [mil] "For Keystone 500x miniature loop terminals"
  round 80 hole 40: 1(0,0)
  silkscreen extent -52,-53 52,52, body extent -49,-49 49,49, height 182
Keystone5010 [mil] "Keystone Multipurpose loops"
  round 87 hole 63: 1(0,0)
  silkscreen extent -70,-70 70,70, body extent -63,-63 63,62, height 319
Keystone5011 [mil] "Keystone Multipurpose loops"
  round 87 hole 63: 1(0,0)
  silkscreen extent -70,-70 70,70, body extent -63,-63 63,62, height 319
Keystone5012 [mil] "Keystone Multipurpose loops"
  round 87 hole 63: 1(0,0)
  silkscreen extent -70,-70 70,70, body extent -63,-63 62,62, height 319
Keystone5013 [mil] "Keystone Multipurpose loops"
  round 87 hole 63: 1(0,0)
  silkscreen extent -70,-70 70,70, body extent -63,-63 62,62, height 319
RDN0011A-MFG [mm]
  rrect42% 1.2x0.475 smd paste-1000 mask-1000: 1(-1.4,1.962) 8(1.4,1.962)
  rrect57% 1.2x0.343 smd paste-1000 mask-1000: 2(-1.4,1.15) 3(-1.4,0.65) 6(1.4,0.65) 7(1.4,1.15)
  rrect13% 1.562x2.15 smd paste-1000 mask-1000: 4(-1.2,-1) 5(1.2,-1)
  rrect57% 0.292x0.9 smd paste-1000 mask-1000: 9(0.5,2.05) 11(-0.5,2.05)
  round 0.504 smd paste-1000 mask-1000: 10(0,1.005)
  Top Layer region: -0.2,2.4 -0.2,2.42 -0.185,2.457 -0.157,2.485 -0.12,2.5 -0.1,2.5 0.1,2.5 0.12,2.5 0.157,2.485 0.185,2.457 0.2,2.42 0.2,2.4 0.2,1.515 0.201,1.507 0.207,1.493 0.218,1.482 0.232,1.476 0.24,1.475 0.248,1.475 0.263,1.469 0.265,1.467 0.265,-2.032 0.237,-2.06 0.2,-2.075 0.18,-2.075 -0.18,-2.075 -0.2,-2.075 -0.237,-2.06 -0.263,-2.034 -0.263,1.469 -0.248,1.475 -0.24,1.475 -0.232,1.476 -0.218,1.482 -0.207,1.493 -0.201,1.507 -0.2,1.515
  silkscreen extent -2.55,-2.42 2.1,2.6, body extent -2.1,-2.4 2.1,2.6, height 0.25
RHB0032E-MFG [mm]
  rrect40% 0.6x0.25 smd: 1(-2.4,1.75) 2(-2.4,1.25) 3(-2.4,0.75) 4(-2.4,0.25) 5(-2.4,-0.25) 6(-2.4,-0.75) 7(-2.4,-1.25) 8(-2.4,-1.75) 17(2.4,-1.75) 18(2.4,-1.25) 19(2.4,-0.75) 20(2.4,-0.25) 21(2.4,0.25) 22(2.4,0.75) 23(2.4,1.25) 24(2.4,1.75)
  rrect40% 0.25x0.6 smd: 9(-1.75,-2.4) 10(-1.25,-2.4) 11(-0.75,-2.4) 12(-0.25,-2.4) 13(0.25,-2.4) 14(0.75,-2.4) 15(1.25,-2.4) 16(1.75,-2.4) 25(1.75,2.4) 26(1.25,2.4) 27(0.75,2.4) 28(0.25,2.4) 29(-0.25,2.4) 30(-0.75,2.4) 31(-1.25,2.4) 32(-1.75,2.4)
  rrect3% 3.45x3.45 smd: 33(0,0)
  silkscreen extent -3.07,-2.55 2.55,2.55, body extent -2.8,-2.8 2.8,2.8, height 0.25
SAMTEC_FTSH-105-01-X-DV-K [mm] "Header(Shrouded), 1.27mm, 5x2, SMT"
  rect 2.79x0.74 smd: 1(-2.035,2.54) 2(2.035,2.54) 3(-2.035,1.27) 4(2.035,1.27) 5(-2.035,0) 6(2.035,0) 7(-2.035,-1.27) 8(2.035,-1.27) 9(-2.035,-2.54) 10(2.035,-2.54)
  silkscreen extent -4.41,-3.48 3.73,3.48, body extent -2.92,-3.18 2.92,3.17, height 6.13
SMB [mil] "Molded Diode, 2-Leads, Body 5.4x3.6mm, IPC Medium Density, based on OnSemi component dimensions"
  rect 85x107.99 smd: 1(-87.01,0) 2(87.01,0)
  silkscreen extent -155,-148 125,82, body extent -106,-71 106,71, height 91
SMB-Bi [mil] "Molded Diode, 2-Leads, Body 5.4x3.6mm, IPC Medium Density, based on OnSemi component dimensions"
  rect 85x107.99 smd: 1(-87.01,0) 2(87.01,0)
  silkscreen extent -125,-79 125,79, body extent -104,-73 104,73, height 89
TI_Stacked_Overlay_Small [mil]
  silkscreen extent -418,-98 418,98
WCAP-ATUL_D10H20 [mm] "Aluminum Electrolytic Capacitors, 10x20mm"
  rrect50% 1.4x1.4 hole 0.9: 1(2.5,0)
  round 1.4 hole 0.9: 2(-2.5,0)
  silkscreen extent -5.25,-5.25 5.25,5.25, body extent -4.99,-5 5,5, height 20.31
WCAP-CSGP_0402_L1W0.5H0.5 [mm] "Ceramic Capacitors, body 1x0.5mm"
  rect 0.5x0.5 smd mask+0.038: 1(-0.5,0) 2(0.5,0)
  silkscreen extent -0.13,-0.25 0.13,0.25, body extent -0.5,-0.25 0.5,0.25, height 0.5
WCAP-CSGP_0603_L1.6W0.8H0.8_REFLOW [mm] "Ceramic Capacitors, body 1.6x0.8mm"
  rect 0.8x0.8 smd mask+0.038: 1(-0.75,0) 2(0.75,0)
  silkscreen extent -0.11,-0.39 0.12,0.41, body extent -0.8,-0.4 0.8,0.4, height 0.8
WCAP-CSGP_1206_L3.2W1.6H1.6 [mm] "Ceramic Capacitors, body 3.2x1.6mm"
  rect 0.9x1.6 smd: 1(-1.55,0) 2(1.55,0)
  silkscreen extent -0.8,-0.95 0.8,0.95, body extent -1.6,-0.8 1.6,0.8, height 1.6
WCAP-CSGP_1812_L4.5W3.2H2.5 [mm] "Ceramic Capacitors, body 4.5x3.2mm"
  rect 0.9x3.8 smd: 1(-2.2,0) 2(2.2,0)
  silkscreen extent -1.45,-1.8 1.45,1.8, body extent -2.25,-1.6 2.25,1.6, height 2.5
WE-LHMI_1335 [mm] "Werth"
  rect 3.1x3.5 smd: 1(-5.55,0) 2(5.55,0)
  silkscreen extent -6.6,-6.6 6.6,6.6, body extent -6.45,-6.45 6.45,6.45, height 3.5
WEEE_Minimum [mil] "WEEElie bin"
  silkscreen extent -95,-172 99,104
WL-SMCW_GREEN [mm] "WURTH"
  rect 0.8x0.8 smd: 1(-0.8,0) 2(0.8,0)
  silkscreen extent -1.9,-0.8 1.2,1.65, body extent -0.85,-0.45 0.85,0.45, height 0.8
WL-SMCW_RED [mm] "WURTH"
  rect 0.8x0.8 smd: 1(-0.8,0) 2(0.8,0)
  silkscreen extent -1.9,-0.8 1.2,1.65, body extent -0.85,-0.45 0.85,0.45, height 0.8
Wurth_60900213421 [mil] "Shunt, 2.54mm, Black"
  round 1 on Mech3: 0(0,0)
  body extent -98,-48 98,48, height 338
WURTH_61300211121 [mm] "Header, 2.54mm, 2x1, TH"
  rrect50% 1.65x1.65 hole 1.15: 1(-1.27,0)
  round 1.65 hole 1.15: 2(1.27,0)
  silkscreen extent -2.54,-1.27 2.54,2.03, body extent -2.54,-1.27 2.54,1.27, height 8.54
WURTH_61300411121 [mm] "Header, 2.54mm, 4x1, TH"
  rrect50% 1.65x1.65 hole 1.15: 1(-3.81,0)
  round 1.65 hole 1.15: 2(-1.27,0) 3(1.27,0) 4(3.81,0)
  silkscreen extent -5.08,-1.27 5.08,1.9, body extent -5.08,-1.27 5.08,1.27, height 8.54

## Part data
C1: library part CMP-0119380-1, "WCAP-CSGP Multilayer Ceramic Chip Capacitor, General Purpose, size 0603, X7R Class II, 470nF, 25VDC", Capacitance Tolerance=+/-10%, Case/Size Code=0603, Insulation Resistance=1.1GOhm, Manufacturer="Wurth Elektronik", Operating Temperature Max=125°C, Operating Temperature Min=-55°C, Rated Voltage (DC)=25V
C2: library part CMP-0120893-1, "10000 pF ±10% 25V Ceramic Capacitor X7R 0603 (1608 Metric)", Digikey Part Number=732-7983-1-ND, Manufacturer="Wurth Electronics", Mouser Part Number=710-885012206065, Operating Temperature Range="-55°C to +125°C", TempCo=15%, Temperature Characteristic=X7R, Tolerance_%=10%, ValueDisplayed=10nF
C3: library part CMP-0860569-1, "CAP, CERM, 10 µF, 25 V,+/- 10%, X5R, 0603", Cap_Case=0603, Manufacturer=MuRata, TempCo=X5R, Tolerance_%=10%, Value2=25V, ValueDisplayed=10µF
C4: library part CMP-0006837-4, "CAP, CERM, 0.1 uF, 50 V, +/- 10%, X7R, 0603", Cap_Case=0603, Manufacturer="Wurth Elektronik", TempCo=X7R, Tolerance_%=10%, Value1=Unknown, Value2=50V, ValueDisplayed=0.1uF
C5 C6 C15 C20: library part CMP-0119636-1, "WCAP-CSGP Multilayer Ceramic Chip Capacitor, General Purpose, size 1206, X7R, 1µF, 50VDC", Capacitance Tolerance=+/-10%, Case/Size Code=1206, Insulation Resistance=0.5GOhm, Manufacturer="Wurth Elektronik", Operating Temperature Max=125°C, Operating Temperature Min=-55°C, Rated Voltage (DC)=50V
C7 C21: library part CMP-0119297-1, "WCAP-CSGP Multilayer Ceramic Chip Capacitor, General Purpose, size 0402, X7R, 10nF, 50VDC", Capacitance Tolerance=+/-10%, Case/Size Code=0402, Insulation Resistance=10GOhm, Manufacturer="Wurth Elektronik", Operating Temperature Max=125°C, Operating Temperature Min=-55°C, Rated Voltage (DC)=50V
C8 C22: library part CMP-0119291-1, "WCAP-CSGP Multilayer Ceramic Chip Capacitor, General Purpose, size 0402, X7R, 1nF, 50VDC", Capacitance Tolerance=+/-10%, Case/Size Code=0402, Insulation Resistance=10GOhm, Manufacturer="Wurth Elektronik", Operating Temperature Max=125°C, Operating Temperature Min=-55°C, Rated Voltage (DC)=50V
C9 C17 C23: library part CMP-0119402-1, "WCAP-CSGP Multilayer Ceramic Chip Capacitor, General Purpose, size 0603, X7R, 100nF, 50VDC", Capacitance Tolerance=+/-10%, Case/Size Code=0603, Insulation Resistance=5GOhm, Manufacturer="Wurth Elektronik", Operating Temperature Max=125°C, Operating Temperature Min=-55°C, Rated Voltage (DC)=50V
C10 C18 C19: library part CMP-0119739-1, "WCAP-CSGP Multilayer Ceramic Chip Capacitor, General Purpose, size 1812, X7R, 2.2µF, 50VDC", Capacitance Tolerance=+/-10%, Case/Size Code=1812, Insulation Resistance=0.2GOhm, Manufacturer="Wurth Elektronik", Operating Temperature Max=125°C, Operating Temperature Min=-55°C, Rated Voltage (DC)=50V
C11: library part CMP-0119398-1, "WCAP-CSGP Multilayer Ceramic Chip Capacitor, General Purpose, size 0603, X7R, 22nF, 50VDC", Capacitance Tolerance=+/-10%, Case/Size Code=0603, Insulation Resistance=10GOhm, Manufacturer="Wurth Elektronik", Operating Temperature Max=125°C, Operating Temperature Min=-55°C, Rated Voltage (DC)=50V
C12: library part CMP-0102582-1, "WCAP-ATUL Aluminum Electrolytic Capacitor, Radial, THT, D10 x H20mm, 82µF, 100V", Capacitance Tolerance=20%, Leakage Current=82uA, Manufacturer="Wurth Elektronik", Operating Temperature Max=105°C, Operating Temperature Min=-40°C, Rated Voltage (DC)=100V, Ripple Current=600mA
C13 C14: library part CMP-0078154-1, "CAP, CERM, 10 µF, 16 V,+/- 20%, X5R, 0805", Cap_Case=0805, Manufacturer="Wurth Elektronik", Supplier Part Number 1=732-7624-1-ND, TempCo=X5R, Tolerance_%=20%, Value2=16V, ValueDisplayed=10µF
C16: library part CMP-0050226-1, "WCAP-CSGP Multilayer Ceramic Chip Capacitor, General Purpose, size 0402, NP0, 47pF, 16VDC", Capacitance Tolerance=+/-5%, Case/Size Code=0402, Insulation Resistance=10GOhm, Manufacturer="Wurth Elektronik", Operating Temperature Max=125°C, Operating Temperature Min=-55°C, Rated Voltage (DC)=16V
C24 C25 C26: library part CMP-0006219-2, "CAP, CERM, 0.1 uF, 6.3 V, +/- 20%, X5R, 0402", Cap_Case=0402, Manufacturer="Wurth Elektronik", Supplier Part Number 1=732-7478-1-ND, TempCo=X5R, Tolerance_%=20%, Value1=Unknown, Value2=6.3V, ValueDisplayed=0.1uF
C27 C28 C29: library part CMP-0006829-4, "CAP, CERM, 0.1 uF, 16 V, +/- 10%, X7R, 0603", Cap_Case=0603, Manufacturer="Wurth Elektronik", Supplier Part Number 1=710-885012206046, TempCo=X7R, Tolerance_%=10%, Value1=Unknown, Value2=16V, ValueDisplayed=0.1uF
C30 C31 C32: library part CMP-0120895-1, "0.022 µF ±10% 50V Ceramic Capacitor X7R 0603 (1608 Metric)", Digikey Part Number=732-8009-1-ND, Manufacturer="Wurth Electronics", Mouser Part Number=710-885012206091, Operating Temperature Range="-55°C to +125°C", TempCo=15%, Temperature Characteristic=X7R, Tolerance_%=10%, ValueDisplayed=22nF
D1 D2: library part CMP-0002894-2, "LED, Green, SMD", Color=green, Manufacturer="Wurth Elektronik", Value1=W, Value2=2V
D3 D4 D5: library part CMP-0002947-3, "LED, Red, SMD", Color=Red, Manufacturer="Wurth Elektronik", Power_TotalModule=72mW, Value1=0.072W, Value2=2V
D6: library part CMP-0098087-1, "58.1V Clamp 10.3A Ipp Tvs Diode Surface Mount SMB", Breakdown Voltage=40V, Clamping Voltage=58.1V, Digikey Part Number=SMBJ36CA-FDICT-ND, Manufacturer="Diodes Inc", Mouser Part Number=621-SMBJ36CA-13-F, Operating Temperature Range="-55°C to +150°C"
D7 D8 D9: library part CMP-0005564-3, "Diode, TVS, Bi, 33 V, SMB", Manufacturer="Diodes Inc.", Value1=600W
D10 D11 D12: library part CMP-0028778-2, "Diode, Schottky, 40 V, 2 A, AEC-Q101, SMB", Manufacturer="ON Semiconductor", Value1=2A, Value2=0.5V
FID1 FID2 FID3: library part CMP-0077181-1, "Fiducial mark.  There is nothing to buy or mount.", Manufacturer=N/A
H1 H2 H3 H4: library part CMP-0003620-1, "Bumpon, Hemisphere, 0.44 X 0.20, Clear", Manufacturer=3M, Supplier Part Number 1=SJ5303-7-ND
J1: library part CMP-0075634-2, "Header(Shrouded), 1.27mm, 5x2, Gold, SMT", Color=Black, Current_A=3.3A, Manufacturer=Samtec, Supplier Part Number 1=SAM8799-ND
J2: library part CMP-0092423-1, "THT Vertical Pin Header WR-PHD, Pitch 2.54 mm, Dual Row, 12 pins", Current_A=3A, Digikey Part Number=732-5297-ND, Manufacturer="Wurth Electronics", Mouser Part Number=710-61301221121, Operating Temperature Range="-40°C to +105°C", Voltage_V=250V
J3: library part CMP-0054798-2, "Header, 2.54 mm, 4x1, Gold, TH", Color=Black, Manufacturer="Wurth Elektronik", Supplier Part Number 1=732-5317-ND
J4 J8 J9 J10: library part CMP-0121282-1, "2 Position Wire to Board Terminal Block Horizontal with Board 0.200\" (5.08mm) Through Hole", Current_A=20A, Digikey Part Number=732-10995-ND, Manufacturer="Wurth Electronics", Mouser Part Number=710-691236510002, Operating Temperature Range="-30°C to +120°C", Voltage_V=300V
J5 J6 J7: library part CMP-0054794-2, "Header, 2.54 mm, 2x1, Gold, TH", Color=Black, Manufacturer="Wurth Elektronik", Supplier Part Number 1=732-5315-ND
L1: library part CMP-0064132-1, "Inductor, Shielded Drum Core, Powdered Iron, 1 uH, 15 A, 0.0027 ohm, SMD", Manufacturer="Wurth Elektronik", Supplier Part Number 1=732-3397-1-ND, Value1="0.0027 ohm", Value2=15A, ValueDisplayed=1uH
Logo1 Logo5 Logo7: library part CMP-0074837-2, "IEC 61010-1 Hot Surface Warning", Manufacturer="Texas Instruments"
Logo2: library part CMP-0074844-2, Manufacturer="Texas Instruments"
Logo3: library part CMP-0074838-1, "Texas Instrument Corporate Signature"
Logo4: library part CMP-0074847-1, "FCC_disclaimer"
LOGO5: library part CMP-0074769-4, Manufacturer="Texas Instruments"
Logo6 Logo8 Logo9: library part CMP-0074836-1, "IEC 61010-1 Caution Warning"
Q1: library part CMP-0000915-2, "MOSFET, N-CH, 80 V, 100 A, DNK0008A (VSON-CLIP-8)", Alternate Manufacturer=None, Manufacturer="Texas Instruments", Supplier Part Number 1=296-37194-1-ND, Value2="48 nC"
